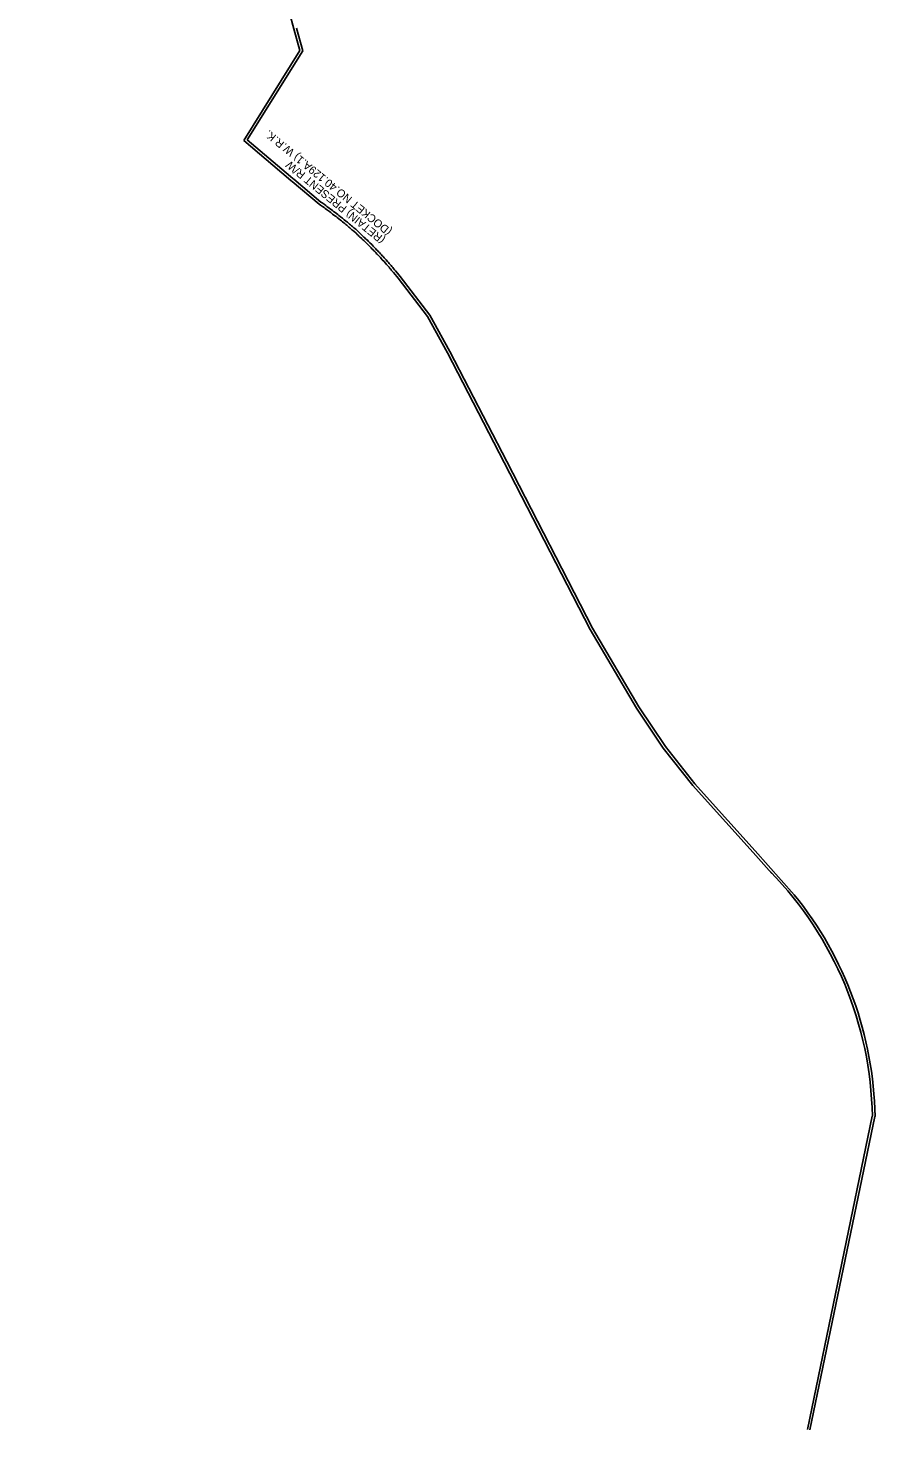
# Model space of a CAD drawing. Extents: x 2004008 to 2024436, y 806921 to 864820.
# Drawn here: x 2016906 to 2017542, y 817439 to 818490 of the extents above; entities that cross this region are included whole.
import ezdxf

# ---------------------------------------------------------------- set-up
doc = ezdxf.new("R2010")
doc.units = 0
for name, color, linetype in [('RD_PD_DR_ErosCtrl', 7, 'Continuous'), ('RD_PD_Final_LnLine', 7, 'Continuous'), ('RD_PD_MedBWall', 7, 'Continuous')]:
    doc.layers.add(name, color=color, linetype=linetype)

msp = doc.modelspace()

# ---------------------------------------------------------------- linework, layer by layer
at = {"layer": 'RD_PD_Final_LnLine'}
for p, q in [((2017110.2, 818472.7), (2017105.8, 818489)), ((2017110.2, 818472.7), (2017068.2, 818405.3)), ((2017490.9, 817439.1), (2017539.6, 817673.9))]:
    msp.add_line(p, q, dxfattribs=at)
for points in [[(2017068.2, 818405.3), (2017101.8, 818376.8), (2017103.7, 818375.1), (2017104.4, 818374.6), (2017124.8, 818357.5), (2017125.8, 818356.8), (2017127.3, 818355.8), (2017128.5, 818354.9), (2017129.3, 818354.3), (2017130.1, 818353.6), (2017131, 818353), (2017131.7, 818352.4), (2017132.4, 818351.9), (2017133.4, 818351.2), (2017134.2, 818350.6), (2017134.8, 818350.1), (2017136.5, 818348.8), (2017137.4, 818348.2), (2017138.2, 818347.5), (2017139.5, 818346.5), (2017140.8, 818345.4), (2017141.5, 818344.9), (2017142.3, 818344.2), (2017143.1, 818343.5), (2017143.9, 818342.9), (2017144.6, 818342.3), (2017145.4, 818341.7), (2017146.2, 818341), (2017147, 818340.3), (2017147.7, 818339.8), (2017148.4, 818339.1), (2017149.3, 818338.4), (2017150.8, 818337.2), (2017152.4, 818335.7), (2017153.2, 818334.9), (2017153.9, 818334.2), (2017154.5, 818333.6), (2017155.3, 818332.9), (2017156.1, 818332.2), (2017156.8, 818331.5), (2017157.5, 818330.8), (2017158.2, 818330.2), (2017158.9, 818329.5), (2017159.7, 818328.7), (2017160.4, 818328), (2017161.4, 818327.1), (2017162.8, 818325.8), (2017163.7, 818324.8), (2017164.3, 818324.1), (2017165.1, 818323.3), (2017165.8, 818322.6), (2017166.4, 818322), (2017167.2, 818321.2), (2017167.8, 818320.4), (2017168.5, 818319.8), (2017169.2, 818319), (2017170, 818318.2), (2017170.6, 818317.5), (2017171.3, 818316.8), (2017172.1, 818315.9), (2017173.4, 818314.6), (2017174.6, 818313.2), (2017175.2, 818312.4), (2017175.8, 818311.8), (2017176.4, 818311), (2017177.2, 818310.2), (2017177.8, 818309.4), (2017178.4, 818308.7), (2017179.1, 818307.9), (2017179.7, 818307.1), (2017180.4, 818306.4), (2017181.8, 818304.7), (2017183, 818303.2), (2017183.9, 818302.1), (2017206.1, 818273.3)], [(2017206.1, 818273.3), (2017220.9, 818246.2), (2017263.6, 818163.8), (2017328, 818038.8), (2017362.7, 817979.7), (2017382.8, 817949.7), (2017405, 817921.7), (2017409.2, 817916.9), (2017450.3, 817871.6), (2017464.3, 817855.8)]]:
    msp.add_lwpolyline(points, dxfattribs=at)
for centre, radius, start, end in [((2016394.4, 818298.4), 736.5, 14.9976, 45.9673), ((2017270.7, 817669.1), 269, 1.0195, 44.2954)]:
    msp.add_arc(centre, radius, start, end, dxfattribs=at)
at = {"layer": 'RD_PD_MedBWall'}
for p, q in [((2017112.4, 818472.4), (2017107.8, 818489.5)), ((2017112.4, 818472.4), (2017070.8, 818405.7)), ((2017492.8, 817438.7), (2017541.6, 817673.7))]:
    msp.add_line(p, q, dxfattribs=at)
for points in [[(2017070.8, 818405.7), (2017103.2, 818378.3), (2017104.9, 818376.7), (2017105.6, 818376.2), (2017126, 818359.1), (2017127, 818358.4), (2017128.4, 818357.4), (2017129.7, 818356.4), (2017130.5, 818355.8), (2017131.3, 818355.2), (2017132.2, 818354.6), (2017132.9, 818354), (2017134.6, 818352.8), (2017135.4, 818352.1), (2017136, 818351.7), (2017137.7, 818350.4), (2017138.6, 818349.7), (2017139.4, 818349.1), (2017140.8, 818348.1), (2017142.1, 818347), (2017142.8, 818346.4), (2017143.5, 818345.8), (2017144.4, 818345), (2017145.2, 818344.4), (2017145.9, 818343.9), (2017146.6, 818343.2), (2017147.5, 818342.5), (2017148.3, 818341.9), (2017148.9, 818341.3), (2017149.7, 818340.7), (2017150.6, 818339.9), (2017152.1, 818338.7), (2017153.7, 818337.2), (2017154.6, 818336.4), (2017155.3, 818335.7), (2017155.9, 818335.1), (2017156.6, 818334.4), (2017157.5, 818333.6), (2017158.2, 818332.9), (2017158.9, 818332.2), (2017159.5, 818331.6), (2017160.3, 818331), (2017161.1, 818330.2), (2017161.8, 818329.5), (2017162.8, 818328.5), (2017164.2, 818327.2), (2017165.2, 818326.1), (2017165.8, 818325.5), (2017166.5, 818324.7), (2017167.2, 818324), (2017167.8, 818323.3), (2017168.6, 818322.5), (2017169.3, 818321.8), (2017169.9, 818321.2), (2017170.7, 818320.4), (2017171.5, 818319.5), (2017172, 818318.9), (2017172.7, 818318.2), (2017173.6, 818317.3), (2017174.9, 818315.9), (2017176.1, 818314.5), (2017176.7, 818313.7), (2017177.3, 818313.1), (2017177.9, 818312.3), (2017178.7, 818311.5), (2017179.3, 818310.7), (2017180, 818310), (2017180.6, 818309.2), (2017181.3, 818308.4), (2017181.9, 818307.6), (2017183.4, 818305.9), (2017184.6, 818304.5), (2017185.5, 818303.3), (2017207.8, 818274.4)], [(2017207.8, 818274.4), (2017222.7, 818247.2), (2017265.4, 818164.7), (2017329.8, 818039.8), (2017364.4, 817980.7), (2017384.4, 817950.9), (2017406.5, 817923), (2017410.7, 817918.2), (2017451.7, 817872.9), (2017481.1, 817839.9)]]:
    msp.add_lwpolyline(points, dxfattribs=at)
msp.add_arc((2017270.7, 817669.1), 271, 0.9722, 39.0749, dxfattribs=at)

# ---------------------------------------------------------------- texts
at = {"layer": 'RD_PD_DR_ErosCtrl'}
for s, p in [('(DOCKET NO.40.129A.1) W.R.K.', (2017179.7, 818338.1)), ('(RETAIN) PRESENT R/W', (2017174.7, 818331.9))]:
    msp.add_text(s, height=6, rotation=140.8523, dxfattribs=at).set_placement(p)

doc.saveas('drawing.dxf')
